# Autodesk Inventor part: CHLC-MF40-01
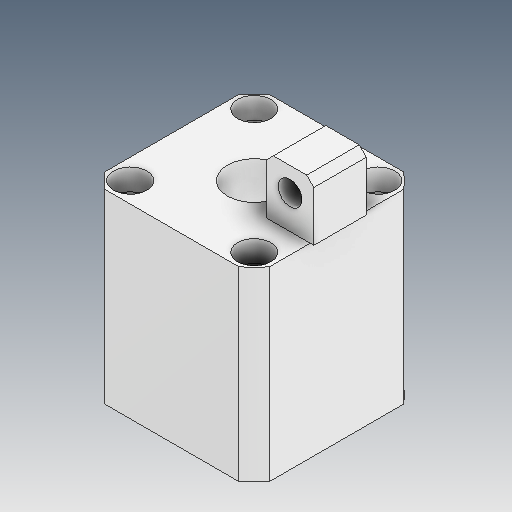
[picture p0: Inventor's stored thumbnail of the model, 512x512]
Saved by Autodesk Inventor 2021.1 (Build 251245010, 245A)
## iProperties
Created: 2021-05
Part Number: CHLC-MF40-01
Material: Ogólny
Document SubType Name: Modeling
Designer: user
Density: 1 g/cm^3
Appearance: Domyślna
Author: user
Revision Number: ÈÎºÎ
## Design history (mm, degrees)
feature "ÊäÈë1"
node "Bryła1"
